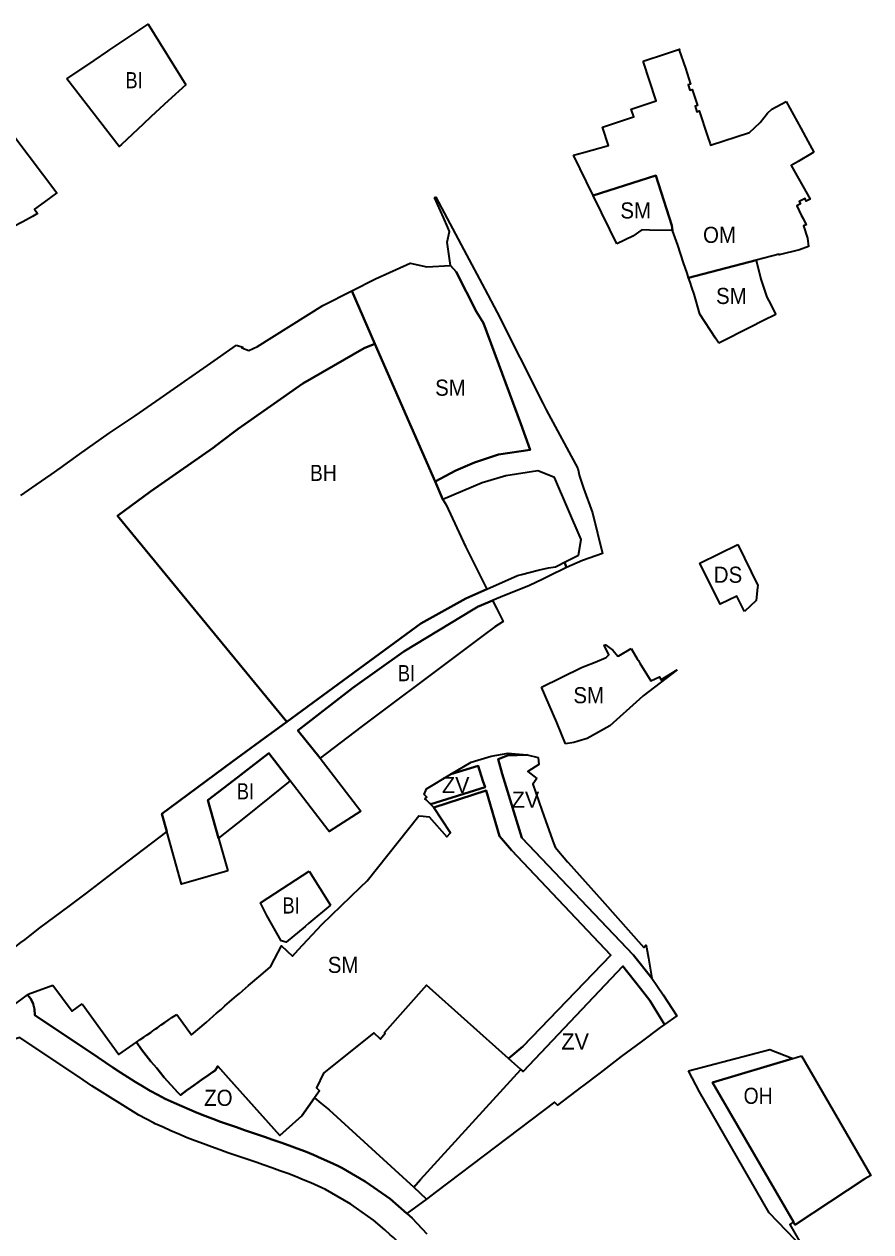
# Model space of a CAD drawing. Extents: x -650971 to -642489, y -1074311 to -1062745.
# Drawn here: x -648072 to -647441, y -1071601 to -1070702 of the extents above; entities that cross this region are included whole.
import ezdxf

# ---------------------------------------------------------------- set-up
doc = ezdxf.new("R2010")
doc.units = 0
doc.header["$LTSCALE"] = 4.8
for name, color, linetype, lineweight in [('1', 7, 'Continuous', 35), ('10', 7, 'Continuous', 35), ('12', 7, 'Continuous', 35), ('15', 7, 'Continuous', 35), ('18', 7, 'Continuous', 35), ('2', 7, 'Continuous', 35), ('24', 7, 'Continuous', 35), ('40', 7, 'Continuous', 35), ('42', 7, 'Continuous', 35), ('62', 7, 'Continuous', 35)]:
    doc.layers.add(name, color=color, linetype=linetype, lineweight=lineweight)

msp = doc.modelspace()

# ---------------------------------------------------------------- linework, layer by layer
at = {"layer": '1'}
for points in [[(-647875.939, -1071221.104), (-648001.922, -1071067.83), (-647977.41, -1071049.74), (-647930.7, -1071017.18), (-647925.216, -1071013.033), (-647912.11, -1071003.11), (-647864.03, -1070969.3), (-647818.33, -1070942.91), (-647810.243, -1070939.825), (-647765.408, -1071042.223), (-647759.52, -1071055.67), (-647757.19, -1071059.66)], [(-647757.19, -1071059.66), (-647742.64, -1071090.72), (-647726.74, -1071122.48)], [(-647726.74, -1071122.48), (-647742.35, -1071129.43), (-647775.982, -1071148.001), (-647875.939, -1071221.104)]]:
    msp.add_lwpolyline(points, dxfattribs=at)
at = {"layer": '10'}
msp.add_line((-647498.8, -1071471.94), (-647492.3, -1071470), dxfattribs=at)
for points in [[(-647498.271, -1071593.544), (-647558.654, -1071489.738), (-647498.8, -1071471.94)], [(-647492.3, -1071470), (-647440.67, -1071558.93), (-647445.11, -1071561.48), (-647497.04, -1071595.66), (-647498.271, -1071593.544)]]:
    msp.add_lwpolyline(points, dxfattribs=at)
at = {"layer": '12'}
for points in [[(-647610.33, -1070729.281), (-647593.6, -1070723.68), (-647583.22, -1070720.2), (-647583.221, -1070720.205)], [(-647583.221, -1070720.205), (-647583.38, -1070720.9), (-647578.79, -1070734.33), (-647575.09, -1070746.33), (-647576.81, -1070746.86), (-647575.58, -1070750.83), (-647573.88, -1070750.25), (-647569.92, -1070762.24), (-647571.63, -1070762.82), (-647570.27, -1070766.86), (-647568.55, -1070766.29), (-647562.274, -1070785.087), (-647560.38, -1070790.77), (-647560.06, -1070791.72), (-647531.05, -1070782.23), (-647523.07, -1070774.86), (-647517.61, -1070767.89), (-647514.49, -1070764.93), (-647503.76, -1070759.31)], [(-647662.26, -1070799.23), (-647654.89, -1070797.23), (-647636.12, -1070792.13), (-647640.66, -1070778.47), (-647619.12, -1070771.28), (-647617.36, -1070770.69), (-647619.2, -1070764.85), (-647600.53, -1070758.65), (-647610.33, -1070729.281)], [(-647503.76, -1070759.31), (-647492.81, -1070779.18), (-647487.67, -1070788.86), (-647483.16, -1070797.07)], [(-647588.4, -1070855.25), (-647588.89, -1070851.67), (-647600.8, -1070814.27), (-647647.571, -1070829.133), (-647662.26, -1070799.23)], [(-647483.16, -1070797.07), (-647494.88, -1070803.86), (-647500.07, -1070806.87), (-647485.9, -1070832), (-647488.75, -1070833.37), (-647489.55, -1070831.53), (-647494.03, -1070833.64), (-647493.16, -1070835.5), (-647495.93, -1070836.86), (-647494.1, -1070840.58), (-647492.48, -1070843.88), (-647491.19, -1070846.49), (-647488.8, -1070851.12), (-647490.92, -1070851.82), (-647487.91, -1070860.91)], [(-647576.469, -1070890.564), (-647577.59, -1070887.19), (-647580.22, -1070879.3), (-647584.6, -1070866.3), (-647588.4, -1070855.25)], [(-647487.91, -1070860.91), (-647487.16, -1070867.32), (-647493.9, -1070869.71), (-647508.96, -1070873.41), (-647509.1, -1070872.96), (-647526.13, -1070877.41), (-647576.469, -1070890.564)]]:
    msp.add_lwpolyline(points, dxfattribs=at)
at = {"layer": '15'}
for points in [[(-647765.72, -1070830.64), (-647764.84, -1070830.47), (-647743.97, -1070869.72)], [(-647756.45, -1070863.95), (-647754.6, -1070856.11), (-647755.87, -1070853.02), (-647759.08, -1070845.74), (-647765.72, -1070830.64)], [(-647765.408, -1071042.223), (-647750, -1071034), (-647736, -1071028), (-647718, -1071022), (-647694.54, -1071018.549), (-647701.45, -1070999.4), (-647729.27, -1070924.35), (-647734.48, -1070915.94), (-647749.75, -1070886.1), (-647753.81, -1070881.3), (-647756.45, -1070863.95)], [(-647743.97, -1070869.72), (-647728.35, -1070899.11), (-647719.06, -1070916.45), (-647685.1, -1070983.93), (-647682.515, -1070988.758)], [(-647682.515, -1070988.758), (-647659.01, -1071032.66), (-647657.699, -1071038.232), (-647654.747, -1071047.095), (-647648.106, -1071065.551), (-647640.727, -1071095.819), (-647655.47, -1071100.98), (-647667.35, -1071106.38), (-647669.02, -1071102.33), (-647658.55, -1071097.02)], [(-647676.963, -1071039.013), (-647688.9, -1071034.18), (-647712.74, -1071037.99), (-647730.17, -1071043.21), (-647759.52, -1071055.67), (-647765.408, -1071042.223)], [(-647658.55, -1071097.02), (-647656.443, -1071085.369), (-647676.45, -1071039.22), (-647676.9, -1071039.03), (-647676.963, -1071039.013)], [(-647726.74, -1071122.48), (-647703.96, -1071112.11), (-647701.04, -1071111.41), (-647688.45, -1071108.38), (-647680.82, -1071106.54), (-647675.64, -1071105.71), (-647674.17, -1071104.97), (-647669.02, -1071102.33), (-647667.35, -1071106.38)], [(-647667.35, -1071106.38), (-647680.64, -1071112.77), (-647684.15, -1071114.47), (-647685.55, -1071115.14), (-647695.08, -1071119.72), (-647716.51, -1071128.48), (-647722.51, -1071130.93)], [(-647875.939, -1071221.104), (-647775.982, -1071148.001), (-647742.35, -1071129.43), (-647726.74, -1071122.48)], [(-647722.51, -1071130.93), (-647732.58, -1071135.04), (-647733.38, -1071135.37), (-647737.027, -1071137.593), (-647788.66, -1071168.8), (-647826.56, -1071195.86), (-647867.586, -1071227.694), (-647850.956, -1071248.208), (-647820.698, -1071287.83)], [(-647965.26, -1071302.86), (-647968.896, -1071289.779), (-647916.208, -1071250.662), (-647895.959, -1071235.746), (-647875.939, -1071221.104)], [(-647873.25, -1071265.17), (-647889.22, -1071244.48), (-647915.6, -1071264.95), (-647934.6, -1071279.45), (-647926.689, -1071307.809), (-647919.88, -1071332.23)], [(-647753.647, -1071260.178), (-647738.56, -1071251.13), (-647723.57, -1071246.66), (-647710.94, -1071244.65), (-647705.59, -1071245.08), (-647696.81, -1071245.79)], [(-647696.81, -1071245.79), (-647711.447, -1071246.332), (-647718.342, -1071248.972), (-647715.355, -1071259.885), (-647700.816, -1071307.512), (-647617.49, -1071394.901), (-647603.9, -1071412.1)], [(-647772.97, -1071278.43), (-647768.445, -1071282.6), (-647728.006, -1071269.975), (-647729.795, -1071265.066), (-647733.15, -1071254.081), (-647753.647, -1071260.178)], [(-647820.698, -1071287.83), (-647844.296, -1071302.757), (-647845.18, -1071301.54), (-647873.25, -1071265.17)], [(-647766.35, -1071285.11), (-647772.07, -1071279.33), (-647772.97, -1071278.43)], [(-647710.546, -1071472.023), (-647700.078, -1071462.96), (-647634.524, -1071394.901), (-647708.429, -1071316.821), (-647717.363, -1071306.29), (-647727.368, -1071272.362), (-647766.35, -1071285.11)], [(-647919.88, -1071332.23), (-647934.51, -1071336.37), (-647954.38, -1071342), (-647965.26, -1071302.86)], [(-647594.43, -1071446.543), (-647605.292, -1071428.816), (-647612.269, -1071419.742), (-647625.428, -1071403.267), (-647699.767, -1071481.617), (-647701.415, -1071480.15), (-647710.546, -1071472.023)], [(-647603.9, -1071412.1), (-647595.335, -1071424.564), (-647585.273, -1071440.044), (-647594.43, -1071446.543)], [(-647576.471, -1071481.091), (-647515.87, -1071465.25), (-647498.8, -1071471.94)], [(-647498.8, -1071471.94), (-647558.654, -1071489.738), (-647498.271, -1071593.544)], [(-647490.561, -1071613.609), (-647516.376, -1071586.89), (-647568.35, -1071496.656), (-647576.471, -1071481.091)], [(-647498.271, -1071593.544), (-647501.11, -1071595.45), (-647493.6, -1071608.5), (-647490.561, -1071613.609)]]:
    msp.add_lwpolyline(points, dxfattribs=at)
at = {"layer": '18'}
msp.add_line((-647576.469, -1070890.564), (-647526.13, -1070877.41), dxfattribs=at)
for points in [[(-647647.571, -1070829.133), (-647600.8, -1070814.27), (-647588.89, -1070851.67), (-647588.4, -1070855.25)], [(-647629.92, -1070865.35), (-647635.09, -1070854.54), (-647647.571, -1070829.133)], [(-647588.4, -1070855.25), (-647605.64, -1070854.99), (-647611.3, -1070854.9), (-647618.01, -1070859.42), (-647629.92, -1070865.35)], [(-647827.527, -1070900.351), (-647809.74, -1070891.31), (-647783.95, -1070879.58), (-647771.47, -1070882.27), (-647753.81, -1070881.3)], [(-647753.81, -1070881.3), (-647749.75, -1070886.1), (-647734.48, -1070915.94), (-647729.27, -1070924.35), (-647701.45, -1070999.4), (-647694.54, -1071018.549), (-647718, -1071022), (-647736, -1071028), (-647750, -1071034), (-647765.408, -1071042.223), (-647810.243, -1070939.825), (-647827.527, -1070900.351)], [(-647526.13, -1070877.41), (-647522.74, -1070891.48), (-647518.12, -1070905.05), (-647516.66, -1070907.8), (-647511.37, -1070917.79)], [(-647553.94, -1070939.11), (-647556.52, -1070935.59), (-647568.2, -1070917.54), (-647572.32, -1070902.72), (-647574.09, -1070897.7), (-647575.35, -1070893.91), (-647576.469, -1070890.564)], [(-647511.37, -1070917.79), (-647511.91, -1070918.07), (-647513.96, -1070919.09), (-647518.08, -1070921.16), (-647533.31, -1070928.79), (-647550.59, -1070937.45), (-647553.94, -1070939.11)], [(-647686.01, -1071195.35), (-647656.25, -1071180.86), (-647653.85, -1071179.87), (-647646.09, -1071176.68), (-647637.87, -1071173.29), (-647635.93, -1071171.22), (-647639.32, -1071164.22), (-647638.46, -1071163.89), (-647632.93, -1071167.71), (-647629.09, -1071172.4), (-647628.39, -1071172.05), (-647619.34, -1071166.709)], [(-647619.34, -1071166.709), (-647614.732, -1071174.222), (-647613.91, -1071175.57), (-647612.695, -1071177.542), (-647604.576, -1071190.781), (-647598.215, -1071187.608), (-647597.164, -1071189.857), (-647584.92, -1071182.54)], [(-647584.92, -1071182.54), (-647610.4, -1071201.91), (-647613.09, -1071204.33), (-647635.17, -1071224.18), (-647651.93, -1071233.57), (-647658.78, -1071235.63), (-647661.99, -1071236.62), (-647668.226, -1071237.57)], [(-647668.226, -1071237.57), (-647674.6, -1071221.71), (-647686.01, -1071195.35)], [(-647766.35, -1071285.11), (-647727.368, -1071272.362), (-647717.363, -1071306.29), (-647708.429, -1071316.821), (-647634.524, -1071394.901), (-647700.078, -1071462.96), (-647710.546, -1071472.023)], [(-647885.05, -1071397.88), (-647879.76, -1071387.96), (-647871.68, -1071395.59), (-647867.45, -1071390.95), (-647849.86, -1071372.18), (-647820.93, -1071344.25), (-647815.95, -1071339.71), (-647777.4, -1071291.32), (-647774.14, -1071291.34), (-647769.85, -1071291.91), (-647756.67, -1071306.77), (-647753.89, -1071303.94), (-647766.35, -1071285.11)], [(-647957.906, -1071439.06), (-647946.78, -1071454.23), (-647936.065, -1071444.983), (-647930.38, -1071440.08), (-647928.16, -1071438.17), (-647924.87, -1071435.33), (-647921.96, -1071432.81), (-647913.31, -1071425.35), (-647911.04, -1071423.39), (-647904.3, -1071417.58), (-647895.29, -1071409.81), (-647888.11, -1071403.61), (-647885.05, -1071397.88)], [(-647710.546, -1071472.023), (-647771.82, -1071417.42), (-647803.1, -1071452.66), (-647802.53, -1071453.19), (-647806.15, -1071457.48), (-647810.97, -1071452.92), (-647848.4, -1071482.78), (-647853.77, -1071493.78), (-647851.45, -1071495.96), (-647855.23, -1071501.297)], [(-647987.8, -1071459.68), (-647985.06, -1071457.79), (-647982.46, -1071456), (-647979.88, -1071454.22), (-647977.28, -1071452.43), (-647974.66, -1071450.62), (-647973.84, -1071450.05), (-647972.02, -1071448.79), (-647969.35, -1071446.96), (-647966.77, -1071445.17), (-647964.14, -1071443.36), (-647961.4, -1071441.471), (-647957.906, -1071439.06)], [(-647855.23, -1071501.297), (-647864.69, -1071514.65), (-647876.27, -1071524.96), (-647881.16, -1071529.25), (-647919.22, -1071486.5), (-647927.2, -1071477.54), (-647929.26, -1071480.77), (-647931.17, -1071482.12), (-647933.88, -1071484.04), (-647939.31, -1071487.88), (-647944.81, -1071491.78), (-647950.56, -1071495.85), (-647955.14, -1071499.23), (-647957.07, -1071497.13), (-647967.13, -1071486.01), (-647972.76, -1071479), (-647977.13, -1071474.05), (-647984.07, -1071465.1), (-647987.8, -1071459.68)]]:
    msp.add_lwpolyline(points, dxfattribs=at)
at = {"layer": '2'}
msp.add_line((-647859.31, -1071332.34), (-647843.23, -1071357.82), dxfattribs=at)
for points in [[(-648039.82, -1070742.33), (-648019.49, -1070728.65), (-648009.29, -1070721.79), (-648008.28, -1070720.96), (-647979.17, -1070701.65), (-647951.11, -1070746.78)], [(-647951.11, -1070746.78), (-647964.21, -1070758.77), (-647976.97, -1070770.51), (-647982.89, -1070776.05), (-647999.06, -1070791.2), (-648000.85, -1070792.88), (-648039.82, -1070742.33)], [(-648089.27, -1070771.57), (-648047.17, -1070827.35), (-648056.61, -1070834.26), (-648063.76, -1070839.49), (-648061.52, -1070842.68), (-648065.35, -1070844.8), (-648072.59, -1070848.79), (-648074.41, -1070849.79), (-648083.65, -1070854.89), (-648125.2, -1070794.79)], [(-647913.45, -1070940.79), (-647908.63, -1070942.1), (-647909.42, -1070942.63), (-647904.13, -1070944.78), (-647897.76, -1070941.62), (-647848.89, -1070911.21), (-647827.527, -1070900.351), (-647810.243, -1070939.825)], [(-648074.121, -1071052.749), (-648062.53, -1071044.59), (-648051.48, -1071036.97), (-648044.82, -1071032.25), (-648030.24, -1071021.91), (-648008.34, -1071006.32), (-647988.81, -1070993.27), (-647970.19, -1070980.45), (-647952.01, -1070967.82), (-647934.9, -1070955.87), (-647913.45, -1070940.79)], [(-647810.243, -1070939.825), (-647818.33, -1070942.91), (-647864.03, -1070969.3), (-647912.11, -1071003.11), (-647925.216, -1071013.033), (-647930.7, -1071017.18), (-647977.41, -1071049.74), (-648001.922, -1071067.83), (-647875.939, -1071221.104)], [(-647850.956, -1071248.208), (-647867.586, -1071227.694), (-647826.56, -1071195.86), (-647788.66, -1071168.8), (-647737.027, -1071137.593), (-647733.38, -1071135.37), (-647732.58, -1071135.04), (-647722.51, -1071130.93)], [(-647722.51, -1071130.93), (-647719.73, -1071136.48), (-647714.71, -1071146.51), (-647720.85, -1071150.41), (-647723.79, -1071152.61), (-647726.56, -1071154.68), (-647750.34, -1071172.5), (-647820.78, -1071225.25), (-647850.956, -1071248.208)], [(-647875.939, -1071221.104), (-647895.959, -1071235.746), (-647916.208, -1071250.662), (-647968.896, -1071289.779), (-647965.26, -1071302.86)], [(-647926.689, -1071307.809), (-647934.6, -1071279.45), (-647915.6, -1071264.95), (-647889.22, -1071244.48), (-647873.25, -1071265.17)], [(-647873.25, -1071265.17), (-647888.77, -1071277.56), (-647907.92, -1071292.84), (-647926.689, -1071307.809)], [(-647965.26, -1071302.86), (-647994.31, -1071325.03), (-648009.31, -1071336.48), (-648025.39, -1071348.76), (-648038.18, -1071358.51), (-648060.01, -1071374.69), (-648067.27, -1071380.27), (-648071.17, -1071383.26), (-648074.27, -1071385.62), (-648091.92, -1071399.07)], [(-647843.23, -1071357.82), (-647859.44, -1071371.23), (-647862.25, -1071373.55), (-647876.34, -1071385.2), (-647880.14, -1071384.32), (-647890.7, -1071365.52), (-647895.37, -1071355.96), (-647879.09, -1071345.3), (-647859.31, -1071332.34)]]:
    msp.add_lwpolyline(points, dxfattribs=at)
at = {"layer": '24'}
msp.add_line((-648101.203, -1071448.31), (-648069.022, -1071424.443), dxfattribs=at)
for points in [[(-647534.851, -1071139.015), (-647540.48, -1071127.55), (-647553.01, -1071133.68), (-647568.01, -1071102.98), (-647539.817, -1071089.199)], [(-647539.817, -1071089.199), (-647524.95, -1071119.68), (-647525.1, -1071121.25), (-647526.04, -1071130.94), (-647534.851, -1071139.015)], [(-648069.022, -1071424.443), (-648066.623, -1071427.592), (-648064.838, -1071431.28), (-648063.862, -1071435.078), (-648063.593, -1071439.723), (-648016.446, -1071471.268), (-648010.917, -1071474.963), (-648005.399, -1071478.627), (-647999.887, -1071482.241), (-647994.366, -1071485.79), (-647988.829, -1071489.259), (-647983.266, -1071492.628), (-647977.67, -1071495.885), (-647972.035, -1071499.009), (-647966.547, -1071501.883), (-647959.792, -1071504.833), (-647954.016, -1071507.496), (-647948.363, -1071509.96), (-647942.644, -1071512.329), (-647936.866, -1071514.613), (-647931.035, -1071516.824), (-647925.157, -1071518.976), (-647919.238, -1071521.081), (-647913.282, -1071523.152), (-647907.294, -1071525.204), (-647892.363, -1071530.282), (-647886.305, -1071532.36), (-647880.233, -1071534.48), (-647874.155, -1071536.658), (-647868.073, -1071538.911), (-647861.998, -1071541.254), (-647855.937, -1071543.707), (-647849.898, -1071546.282), (-647843.891, -1071549), (-647837.929, -1071551.872), (-647834.953, -1071553.406), (-647817.375, -1071563.458), (-647798.911, -1071576.526), (-647786.379, -1071587.401)], [(-647986.233, -1071514.148), (-648021.015, -1071492.264), (-648027.562, -1071487.894), (-648074.86, -1071456.248), (-648078.539, -1071457.636), (-648081.642, -1071458.215), (-648085.585, -1071458.248), (-648089.539, -1071457.489), (-648093.059, -1071456.066), (-648096.014, -1071454.192), (-648098.259, -1071452.196), (-648101.203, -1071448.31)], [(-647973.938, -1071520.48), (-647975.194, -1071519.932), (-647986.233, -1071514.148)], [(-647802.849, -1071599.589), (-647811.272, -1071592.28), (-647828.141, -1071580.34), (-647847.103, -1071569.497), (-647857.944, -1071564.594), (-647863.611, -1071562.177), (-647869.348, -1071559.856), (-647875.147, -1071557.619), (-647881.001, -1071555.45), (-647886.903, -1071553.336), (-647892.847, -1071551.26), (-647898.827, -1071549.208), (-647913.756, -1071544.132), (-647919.808, -1071542.058), (-647925.874, -1071539.949), (-647931.945, -1071537.788), (-647938.019, -1071535.566), (-647944.088, -1071533.263), (-647950.146, -1071530.869), (-647956.187, -1071528.368), (-647962.2, -1071525.746), (-647967.982, -1071523.081), (-647973.938, -1071520.48)], [(-647786.379, -1071587.401), (-647782.408, -1071590.847), (-647771.408, -1071602.414)], [(-647609.808, -1072001.962), (-647611.779, -1071999.069), (-647613.637, -1071995.081), (-647614.76, -1071990.762), (-647615.083, -1071986.65), (-647614.654, -1071982.238), (-647613.455, -1071978.031), (-647611.514, -1071974.086), (-647743.48, -1071687.426), (-647758.994, -1071653.513), (-647769.498, -1071636.647), (-647782.97, -1071619.278), (-647796.24, -1071605.324), (-647798.8, -1071603.102), (-647802.849, -1071599.589)]]:
    msp.add_lwpolyline(points, dxfattribs=at)
at = {"layer": '40'}
msp.add_line((-647696.81, -1071245.79), (-647688.46, -1071247.65), dxfattribs=at)
for points in [[(-647603.9, -1071412.1), (-647617.49, -1071394.901), (-647700.816, -1071307.512), (-647715.355, -1071259.885), (-647718.342, -1071248.972), (-647711.447, -1071246.332), (-647696.81, -1071245.79)], [(-647688.46, -1071247.65), (-647688.17, -1071253.06), (-647696.35, -1071258.14), (-647689.61, -1071263.51)], [(-647772.97, -1071278.43), (-647771.59, -1071277.36), (-647773.6, -1071275.43), (-647771.76, -1071271.04), (-647753.647, -1071260.178)], [(-647753.647, -1071260.178), (-647733.15, -1071254.081), (-647729.795, -1071265.066), (-647728.006, -1071269.975), (-647768.445, -1071282.6), (-647772.97, -1071278.43)], [(-647689.61, -1071263.51), (-647692.45, -1071267.67), (-647685.74, -1071286.93), (-647681.53, -1071299.02), (-647677, -1071312.01), (-647675.85, -1071314.62), (-647666.78, -1071325.52), (-647666.629, -1071325.351)], [(-647666.629, -1071325.351), (-647666.21, -1071325.89), (-647640.92, -1071354.21), (-647609.85, -1071389.21), (-647608.31, -1071387.63), (-647607.77, -1071388.91), (-647606.39, -1071397.21), (-647603.9, -1071412.1)], [(-647701.415, -1071480.15), (-647699.767, -1071481.617), (-647625.428, -1071403.267), (-647612.269, -1071419.742), (-647605.292, -1071428.816), (-647594.43, -1071446.543)], [(-647594.43, -1071446.543), (-647597.54, -1071448.75), (-647611.82, -1071459.38), (-647626.7, -1071470.46), (-647642.45, -1071482.62), (-647655.517, -1071492.465), (-647656.27, -1071493.04), (-647674.28, -1071506.59), (-647676.51, -1071504.34), (-647764.23, -1071571.01), (-647771.717, -1071576.551), (-647781.31, -1071567.79)], [(-647781.31, -1071567.79), (-647776.13, -1071562.1), (-647701.415, -1071480.15)]]:
    msp.add_lwpolyline(points, dxfattribs=at)
at = {"layer": '42'}
for points in [[(-648069.022, -1071424.443), (-648068.56, -1071424.1), (-648050.25, -1071417.19)], [(-648050.25, -1071417.19), (-648035.87, -1071436.62), (-648028.31, -1071431.32)], [(-647786.379, -1071587.401), (-647798.911, -1071576.526), (-647817.375, -1071563.458), (-647834.953, -1071553.406), (-647837.929, -1071551.872), (-647843.891, -1071549), (-647849.898, -1071546.282), (-647855.937, -1071543.707), (-647861.998, -1071541.254), (-647868.073, -1071538.911), (-647874.155, -1071536.658), (-647880.233, -1071534.48), (-647886.305, -1071532.36), (-647892.363, -1071530.282), (-647907.294, -1071525.204), (-647913.282, -1071523.152), (-647919.238, -1071521.081), (-647925.157, -1071518.976), (-647931.035, -1071516.824), (-647936.866, -1071514.613), (-647942.644, -1071512.329), (-647948.363, -1071509.96), (-647954.016, -1071507.496), (-647959.792, -1071504.833), (-647966.547, -1071501.883), (-647972.035, -1071499.009), (-647977.67, -1071495.885), (-647983.266, -1071492.628), (-647988.829, -1071489.259), (-647994.366, -1071485.79), (-647999.887, -1071482.241), (-648005.399, -1071478.627), (-648010.917, -1071474.963), (-648016.446, -1071471.268), (-648063.593, -1071439.723), (-648063.862, -1071435.078), (-648064.838, -1071431.28), (-648066.623, -1071427.592), (-648069.022, -1071424.443)], [(-648028.31, -1071431.32), (-648000.91, -1071469.01), (-647987.8, -1071459.68)], [(-647987.8, -1071459.68), (-647984.07, -1071465.1), (-647977.13, -1071474.05), (-647972.76, -1071479), (-647967.13, -1071486.01), (-647957.07, -1071497.13), (-647955.14, -1071499.23), (-647950.56, -1071495.85), (-647944.81, -1071491.78), (-647939.31, -1071487.88), (-647933.88, -1071484.04), (-647931.17, -1071482.12), (-647929.26, -1071480.77), (-647927.2, -1071477.54), (-647919.22, -1071486.5), (-647881.16, -1071529.25), (-647876.27, -1071524.96), (-647864.69, -1071514.65), (-647855.23, -1071501.297)], [(-647855.23, -1071501.297), (-647850.55, -1071505.14), (-647844.4, -1071510.2), (-647789.73, -1071560.1), (-647781.31, -1071567.79), (-647771.717, -1071576.551), (-647786.379, -1071587.401)]]:
    msp.add_lwpolyline(points, dxfattribs=at)

# ---------------------------------------------------------------- texts
at = {"layer": '62'}
for s, width, p in [('BI', 0.85, (-647996.127, -1070749.398)), ('SM', 0.95, (-647627.328, -1070846.374)), ('OM', 0.95, (-647565.708, -1070864.552)), ('SM', 0.95, (-647556.006, -1070910.054)), ('SM', 0.95, (-647765.328, -1070978.374)), ('BH', 0.9, (-647858.64, -1071041.819)), ('DS', 0.95, (-647557.693, -1071117.661)), ('BI', 0.85, (-647793.1, -1071190.942)), ('SM', 0.95, (-647662.328, -1071207.374)), ('BI', 0.85, (-647913.1, -1071278.942)), ('BI', 0.85, (-647879.1, -1071363.942)), ('SM', 0.95, (-647845.307, -1071408.18)), ('ZO', 0.95, (-647937.423, -1071507.188)), ('OH', 0.9, (-647535.508, -1071505.684))]:
    msp.add_text(s, height=12, dxfattribs=dict(at, width=width)).set_placement(p)
for p in [(-647760.241, -1071274.214), (-647708.241, -1071285.214), (-647671.241, -1071465.214)]:
    msp.add_text('ZV', height=12, dxfattribs=at).set_placement(p)

doc.saveas('drawing.dxf')
